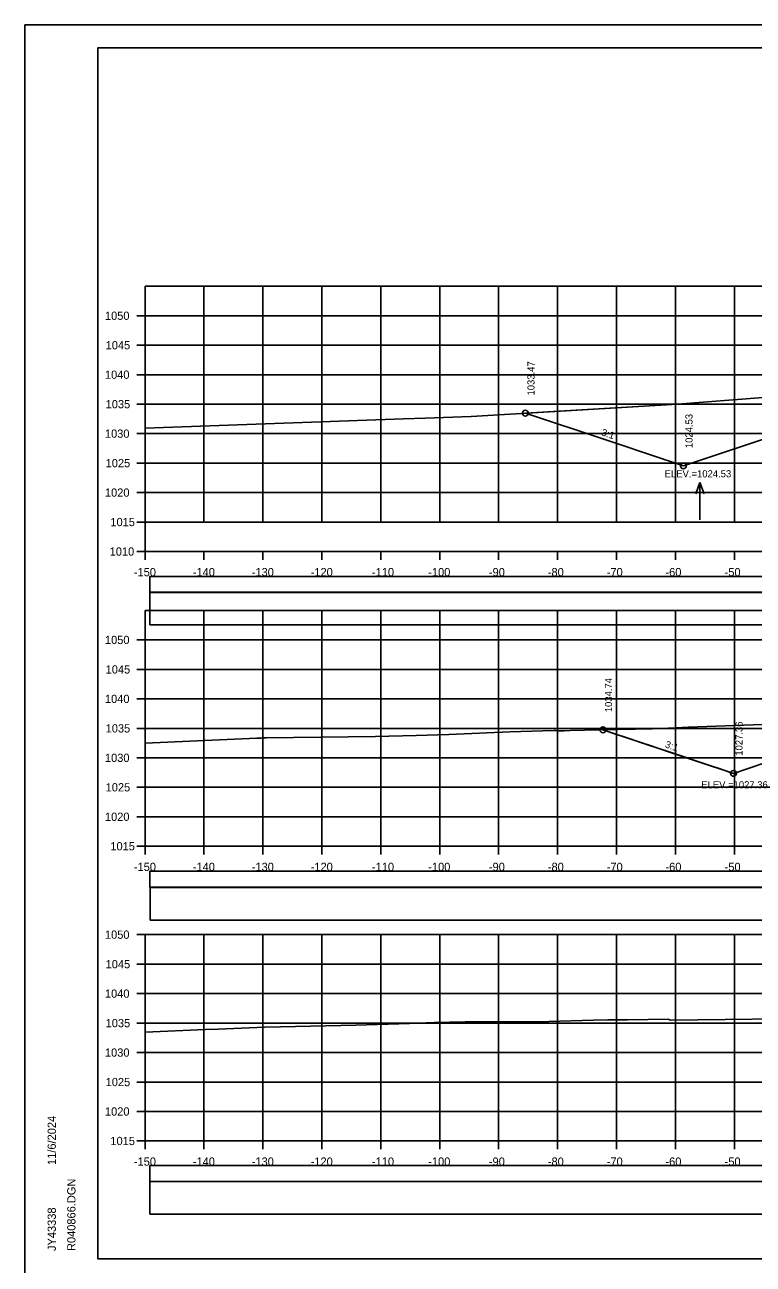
# Model space of a CAD drawing. Extents: x 1370565 to 1374448, y 301010 to 304637.
# Drawn here: x 1373198.4 to 1373322, y 301728.1 to 301938.3 of the extents above; entities that cross this region are included whole.
import ezdxf

# ---------------------------------------------------------------- set-up
doc = ezdxf.new("R2010")
doc.units = 0
for name, color, linetype in [('Default', 7, 'Continuous'), ('R_Axis', 7, 'Continuous'), ('R_Axis Annot', 7, 'Continuous'), ('R_Border', 7, 'Continuous'), ('R_Contours', 7, 'Continuous'), ('R_Drive', 7, 'Continuous'), ('R_Exist Surface', 7, 'Continuous'), ('R_Fin Surface', 7, 'Continuous'), ('R_Grid', 7, 'Continuous'), ('R_No Plot', 7, 'Continuous'), ('R_Water Annot', 7, 'Continuous'), ('R_Xsect Elev', 7, 'Continuous'), ('R_Xsect Slope', 7, 'Continuous')]:
    doc.layers.add(name, color=color, linetype=linetype)

msp = doc.modelspace()

# ---------------------------------------------------------------- linework, layer by layer
at = {"layer": 'Default'}
for points in [[(1373219.61, 301842.01), (1373518.02, 301842.01), (1373518.02, 301844.72), (1373219.61, 301844.72)], [(1373219.61, 301836.55), (1373517.91, 301836.55), (1373517.91, 301842.07), (1373219.61, 301842.07)], [(1373219.61, 301736.55), (1373517.91, 301736.55), (1373517.91, 301742.07), (1373219.61, 301742.07)]]:
    msp.add_lwpolyline(points, close=True, dxfattribs=at)
at = {"layer": 'R_Axis'}
for p, q in [((1373217.41, 301888.97), (1373218.81, 301888.97)), ((1373218.81, 301848.97), (1373218.81, 301888.97)), ((1373217.41, 301883.97), (1373218.81, 301883.97)), ((1373217.41, 301878.97), (1373218.81, 301878.97)), ((1373217.41, 301873.97), (1373218.81, 301873.97)), ((1373217.41, 301868.97), (1373218.81, 301868.97)), ((1373217.41, 301863.97), (1373218.81, 301863.97)), ((1373217.41, 301858.97), (1373218.81, 301858.97)), ((1373217.41, 301853.97), (1373218.81, 301853.97)), ((1373217.41, 301848.97), (1373218.81, 301848.97)), ((1373218.81, 301848.97), (1373518.81, 301848.97)), ((1373218.81, 301847.57), (1373218.81, 301848.97)), ((1373228.81, 301847.57), (1373228.81, 301848.97)), ((1373238.81, 301847.57), (1373238.81, 301848.97)), ((1373248.81, 301847.57), (1373248.81, 301848.97)), ((1373258.81, 301847.57), (1373258.81, 301848.97)), ((1373268.81, 301847.57), (1373268.81, 301848.97)), ((1373278.81, 301847.57), (1373278.81, 301848.97)), ((1373288.81, 301847.57), (1373288.81, 301848.97)), ((1373298.81, 301847.57), (1373298.81, 301848.97)), ((1373308.81, 301847.57), (1373308.81, 301848.97)), ((1373318.81, 301847.57), (1373318.81, 301848.97)), ((1373217.41, 301833.97), (1373218.81, 301833.97)), ((1373218.81, 301798.97), (1373218.81, 301833.97)), ((1373217.41, 301828.97), (1373218.81, 301828.97)), ((1373217.41, 301823.97), (1373218.81, 301823.97)), ((1373217.41, 301818.97), (1373218.81, 301818.97)), ((1373217.41, 301813.97), (1373218.81, 301813.97)), ((1373217.41, 301808.97), (1373218.81, 301808.97)), ((1373217.41, 301803.97), (1373218.81, 301803.97)), ((1373217.41, 301798.97), (1373218.81, 301798.97)), ((1373218.81, 301798.97), (1373518.81, 301798.97)), ((1373218.81, 301797.57), (1373218.81, 301798.97)), ((1373228.81, 301797.57), (1373228.81, 301798.97)), ((1373238.81, 301797.57), (1373238.81, 301798.97)), ((1373248.81, 301797.57), (1373248.81, 301798.97)), ((1373258.81, 301797.57), (1373258.81, 301798.97)), ((1373268.81, 301797.57), (1373268.81, 301798.97)), ((1373278.81, 301797.57), (1373278.81, 301798.97)), ((1373288.81, 301797.57), (1373288.81, 301798.97)), ((1373298.81, 301797.57), (1373298.81, 301798.97)), ((1373308.81, 301797.57), (1373308.81, 301798.97)), ((1373318.81, 301797.57), (1373318.81, 301798.97)), ((1373217.41, 301783.97), (1373218.81, 301783.97)), ((1373218.81, 301748.97), (1373218.81, 301783.97)), ((1373217.41, 301778.97), (1373218.81, 301778.97)), ((1373217.41, 301773.97), (1373218.81, 301773.97)), ((1373217.41, 301768.97), (1373218.81, 301768.97)), ((1373217.41, 301763.97), (1373218.81, 301763.97)), ((1373217.41, 301758.97), (1373218.81, 301758.97)), ((1373217.41, 301753.97), (1373218.81, 301753.97)), ((1373217.41, 301748.97), (1373218.81, 301748.97)), ((1373218.81, 301748.97), (1373518.81, 301748.97)), ((1373218.81, 301747.57), (1373218.81, 301748.97)), ((1373228.81, 301747.57), (1373228.81, 301748.97)), ((1373238.81, 301747.57), (1373238.81, 301748.97)), ((1373248.81, 301747.57), (1373248.81, 301748.97)), ((1373258.81, 301747.57), (1373258.81, 301748.97)), ((1373268.81, 301747.57), (1373268.81, 301748.97)), ((1373278.81, 301747.57), (1373278.81, 301748.97)), ((1373288.81, 301747.57), (1373288.81, 301748.97)), ((1373298.81, 301747.57), (1373298.81, 301748.97)), ((1373308.81, 301747.57), (1373308.81, 301748.97)), ((1373318.81, 301747.57), (1373318.81, 301748.97))]:
    msp.add_line(p, q, dxfattribs=at)
at = {"layer": 'R_Border'}
for p, q in [((1373210.81, 301934.43), (1373526.99, 301934.43)), ((1373210.81, 301728.97), (1373210.81, 301934.43)), ((1373210.81, 301728.97), (1373210.81, 301728.97)), ((1373526.99, 301728.97), (1373210.81, 301728.97))]:
    msp.add_line(p, q, dxfattribs=at)
at = {"layer": 'R_Contours'}
for points in [[(1373337.3, 301875.61), (1373330.04, 301875.36), (1373327.7, 301875.26), (1373323.67, 301875.09), (1373309.17, 301873.95), (1373283.35, 301872.44)], [(1373283.35, 301872.44), (1373296.85, 301867.95), (1373306.62, 301864.69), (1373307.06, 301864.54), (1373307.49, 301864.4), (1373310.16, 301863.51), (1373335.99, 301872.12), (1373339.81, 301873.39), (1373340.96, 301873.58), (1373342.79, 301873.89)], [(1373296.51, 301818.71), (1373298.84, 301817.94), (1373300.26, 301817.46), (1373302.75, 301816.63), (1373303.04, 301816.54), (1373303.63, 301816.34), (1373304.21, 301816.15), (1373307.98, 301814.89), (1373315.08, 301812.52), (1373316.15, 301812.17), (1373318.65, 301811.33), (1373326.66, 301814), (1373329.53, 301814.96), (1373332.85, 301816.06), (1373339.81, 301818.39), (1373340.71, 301818.53), (1373353.42, 301820.65)], [(1373352.45, 301820.64), (1373336.11, 301820.13), (1373326.67, 301819.76), (1373310.97, 301819.15), (1373308.86, 301819.07), (1373304.93, 301818.91), (1373299.01, 301818.77), (1373298.31, 301818.76), (1373296.51, 301818.71)]]:
    msp.add_lwpolyline(points, dxfattribs=at)
at = {"layer": 'R_Drive'}
for points in [[(1373219.61, 301792.01), (1373518.02, 301792.01), (1373518.02, 301794.72), (1373219.61, 301794.72)], [(1373219.61, 301742.07), (1373518.02, 301742.07), (1373518.02, 301744.78), (1373219.61, 301744.78)]]:
    msp.add_lwpolyline(points, close=True, dxfattribs=at)
at = {"layer": 'R_Exist Surface'}
for points in [[(1373218.81, 301869.88), (1373248.65, 301870.97), (1373262.66, 301871.48), (1373266.37, 301871.62), (1373274.15, 301871.9), (1373309.17, 301873.95), (1373323.67, 301875.09)], [(1373289.94, 301818.57), (1373290.96, 301818.58), (1373298.31, 301818.76), (1373299.01, 301818.77), (1373304.93, 301818.91), (1373308.86, 301819.07), (1373310.97, 301819.15), (1373326.67, 301819.76)], [(1373218.81, 301816.47), (1373237.76, 301817.29), (1373238.51, 301817.32), (1373238.85, 301817.34), (1373239.34, 301817.36), (1373257.92, 301817.61), (1373260.18, 301817.67), (1373264.84, 301817.78), (1373270.38, 301817.92), (1373280.71, 301818.36), (1373288.18, 301818.61), (1373288.5, 301818.58), (1373288.92, 301818.55), (1373289.06, 301818.54), (1373289.11, 301818.53), (1373289.94, 301818.57)], [(1373218.81, 301767.4), (1373229.08, 301767.88), (1373231.23, 301767.94), (1373239.15, 301768.28), (1373241.81, 301768.33), (1373254.6, 301768.61), (1373263.7, 301768.91), (1373267.93, 301769.08), (1373273.12, 301769.18), (1373274.59, 301769.17), (1373287.34, 301769.21), (1373294.87, 301769.45), (1373297.32, 301769.51), (1373297.54, 301769.51), (1373300.65, 301769.54), (1373307.61, 301769.61), (1373307.7, 301769.57), (1373307.95, 301769.47), (1373335.77, 301769.82)]]:
    msp.add_lwpolyline(points, dxfattribs=at)
at = {"layer": 'R_Fin Surface'}
for points in [[(1373283.37, 301872.44), (1373296.85, 301867.95), (1373306.62, 301864.69), (1373307.06, 301864.54), (1373307.49, 301864.4), (1373310.16, 301863.51), (1373335.99, 301872.12), (1373339.81, 301873.39), (1373353.81, 301875.73), (1373357.81, 301876.05), (1373368.81, 301876.96), (1373379.81, 301877.87), (1373383.81, 301878.2), (1373397.81, 301875.86), (1373425.23, 301866.73), (1373429.66, 301865.25), (1373443.87, 301872.3), (1373446.06, 301873.45)], [(1373296.07, 301818.86), (1373298.47, 301818.06), (1373299.9, 301817.58), (1373302.41, 301816.75), (1373302.71, 301816.65), (1373303.31, 301816.45), (1373303.9, 301816.25), (1373307.73, 301814.98), (1373314.99, 301812.55), (1373316.09, 301812.19), (1373318.65, 301811.33), (1373326.66, 301814), (1373329.53, 301814.96), (1373332.85, 301816.06), (1373339.81, 301818.39), (1373353.81, 301820.72), (1373357.81, 301821.05), (1373368.81, 301821.98), (1373379.81, 301822.9), (1373383.81, 301823.24), (1373397.81, 301820.91), (1373431.81, 301809.57), (1373444.26, 301815.8)]]:
    msp.add_lwpolyline(points, dxfattribs=at)
msp.add_lwpolyline([(1373219.66, 301786.44), (1373518.08, 301786.44), (1373518.08, 301791.96), (1373219.66, 301791.96)], close=True, dxfattribs=at)
at = {"layer": 'R_Grid'}
for p, q in [((1373218.81, 301893.97), (1373518.81, 301893.97)), ((1373218.81, 301853.97), (1373218.81, 301893.97)), ((1373228.81, 301853.97), (1373228.81, 301893.97)), ((1373238.81, 301853.97), (1373238.81, 301893.97)), ((1373248.81, 301853.97), (1373248.81, 301893.97)), ((1373258.81, 301853.97), (1373258.81, 301893.97)), ((1373268.81, 301853.97), (1373268.81, 301893.97)), ((1373278.81, 301853.97), (1373278.81, 301893.97)), ((1373288.81, 301853.97), (1373288.81, 301893.97)), ((1373298.81, 301853.97), (1373298.81, 301893.97)), ((1373308.81, 301853.97), (1373308.81, 301893.97)), ((1373318.81, 301853.97), (1373318.81, 301893.97)), ((1373218.81, 301888.97), (1373518.81, 301888.97)), ((1373218.81, 301883.97), (1373518.81, 301883.97)), ((1373218.81, 301878.97), (1373518.81, 301878.97)), ((1373218.81, 301873.97), (1373518.81, 301873.97)), ((1373218.81, 301868.97), (1373518.81, 301868.97)), ((1373218.81, 301863.97), (1373518.81, 301863.97)), ((1373218.81, 301858.97), (1373518.81, 301858.97)), ((1373218.81, 301853.97), (1373518.81, 301853.97)), ((1373218.81, 301838.97), (1373518.81, 301838.97)), ((1373218.81, 301798.97), (1373218.81, 301838.97)), ((1373228.81, 301798.97), (1373228.81, 301838.97)), ((1373238.81, 301798.97), (1373238.81, 301838.97)), ((1373248.81, 301798.97), (1373248.81, 301838.97)), ((1373258.81, 301798.97), (1373258.81, 301838.97)), ((1373268.81, 301798.97), (1373268.81, 301838.97)), ((1373278.81, 301798.97), (1373278.81, 301838.97)), ((1373288.81, 301798.97), (1373288.81, 301838.97)), ((1373298.81, 301798.97), (1373298.81, 301838.97)), ((1373308.81, 301798.97), (1373308.81, 301838.97)), ((1373318.81, 301798.97), (1373318.81, 301838.97)), ((1373218.81, 301833.97), (1373518.81, 301833.97)), ((1373218.81, 301828.97), (1373518.81, 301828.97)), ((1373218.81, 301823.97), (1373518.81, 301823.97)), ((1373218.81, 301818.97), (1373518.81, 301818.97)), ((1373218.81, 301813.97), (1373518.81, 301813.97)), ((1373218.81, 301808.97), (1373518.81, 301808.97)), ((1373218.81, 301803.97), (1373518.81, 301803.97)), ((1373218.81, 301798.97), (1373518.81, 301798.97)), ((1373218.81, 301783.97), (1373518.81, 301783.97)), ((1373218.81, 301748.97), (1373218.81, 301783.97)), ((1373228.81, 301748.97), (1373228.81, 301783.97)), ((1373238.81, 301748.97), (1373238.81, 301783.97)), ((1373248.81, 301748.97), (1373248.81, 301783.97)), ((1373258.81, 301748.97), (1373258.81, 301783.97)), ((1373268.81, 301748.97), (1373268.81, 301783.97)), ((1373278.81, 301748.97), (1373278.81, 301783.97)), ((1373288.81, 301748.97), (1373288.81, 301783.97)), ((1373298.81, 301748.97), (1373298.81, 301783.97)), ((1373308.81, 301748.97), (1373308.81, 301783.97)), ((1373318.81, 301748.97), (1373318.81, 301783.97)), ((1373218.81, 301778.97), (1373518.81, 301778.97)), ((1373218.81, 301773.97), (1373518.81, 301773.97)), ((1373218.81, 301768.97), (1373518.81, 301768.97)), ((1373218.81, 301763.97), (1373518.81, 301763.97)), ((1373218.81, 301758.97), (1373518.81, 301758.97)), ((1373218.81, 301753.97), (1373518.81, 301753.97)), ((1373218.81, 301748.97), (1373518.81, 301748.97))]:
    msp.add_line(p, q, dxfattribs=at)
at = {"layer": 'R_No Plot'}
msp.add_line((1373198.41, 301938.33), (1373531.75, 301938.33), dxfattribs=at)
for points in [[(1373198.41, 301938.33), (1373531.75, 301938.33), (1373531.75, 301724.99), (1373198.41, 301724.99)], [(1373444.73, 301934.43), (1373464.35, 301934.43), (1373464.35, 301924.55), (1373480.47, 301924.55), (1373503.67, 301924.55), (1373503.67, 301891.88), (1373526.87, 301891.88), (1373526.99, 301728.97), (1373210.81, 301728.97), (1373210.81, 301934.43)]]:
    msp.add_lwpolyline(points, close=True, dxfattribs=at)
for centre in [(1373283.35, 301872.44), (1373310.16, 301863.51), (1373296.51, 301818.71), (1373318.65, 301811.33)]:
    msp.add_circle(centre, 0.5, dxfattribs=at)
at = {"layer": 'R_Water Annot'}
for p, q in [((1373312.97, 301860.66), (1373312.27, 301858.73)), ((1373312.97, 301854.37), (1373312.97, 301860.66)), ((1373312.97, 301860.66), (1373313.67, 301858.73))]:
    msp.add_line(p, q, dxfattribs=at)

# ---------------------------------------------------------------- texts
at = {"layer": 'R_Axis Annot'}
for s, p in [('1050', (1373212.01, 301888.27)), ('1045', (1373212.13, 301883.27)), ('1040', (1373212.01, 301878.27)), ('1035', (1373212.13, 301873.27)), ('1030', (1373212.01, 301868.27)), ('1025', (1373212.13, 301863.27)), ('1020', (1373212.01, 301858.27)), ('1015', (1373212.93, 301853.27)), ('1010', (1373212.81, 301848.27)), ('-150', (1373216.92, 301844.77)), ('-140', (1373226.92, 301844.77)), ('-130', (1373236.92, 301844.77)), ('-120', (1373246.92, 301844.77)), ('-110', (1373257.32, 301844.77)), ('-100', (1373266.87, 301844.77)), ('-90', (1373277.16, 301844.77)), ('-80', (1373287.16, 301844.77)), ('-70', (1373297.16, 301844.77)), ('-60', (1373307.12, 301844.77)), ('-50', (1373317.16, 301844.77)), ('1050', (1373212.01, 301833.27)), ('1045', (1373212.13, 301828.27)), ('1040', (1373212.01, 301823.27)), ('1035', (1373212.13, 301818.27)), ('1030', (1373212.01, 301813.27)), ('1025', (1373212.13, 301808.27)), ('1020', (1373212.01, 301803.27)), ('1015', (1373212.93, 301798.27)), ('-150', (1373216.92, 301794.77)), ('-140', (1373226.92, 301794.77)), ('-130', (1373236.92, 301794.77)), ('-120', (1373246.92, 301794.77)), ('-110', (1373257.32, 301794.77)), ('-100', (1373266.87, 301794.77)), ('-90', (1373277.16, 301794.77)), ('-80', (1373287.16, 301794.77)), ('-70', (1373297.16, 301794.77)), ('-60', (1373307.12, 301794.77)), ('-50', (1373317.16, 301794.77)), ('1050', (1373212.01, 301783.27)), ('1045', (1373212.13, 301778.27)), ('1040', (1373212.01, 301773.27)), ('1035', (1373212.13, 301768.27)), ('1030', (1373212.01, 301763.27)), ('1025', (1373212.13, 301758.27)), ('1020', (1373212.01, 301753.27)), ('1015', (1373212.93, 301748.27)), ('-150', (1373216.92, 301744.77)), ('-140', (1373226.92, 301744.77)), ('-130', (1373236.92, 301744.77)), ('-120', (1373246.92, 301744.77)), ('-110', (1373257.32, 301744.77)), ('-100', (1373266.87, 301744.77)), ('-90', (1373277.16, 301744.77)), ('-80', (1373287.16, 301744.77)), ('-70', (1373297.16, 301744.77)), ('-60', (1373307.12, 301744.77)), ('-50', (1373317.16, 301744.77))]:
    msp.add_text(s, height=1.4, dxfattribs=at).set_placement(p)
at = {"layer": 'R_Border'}
for s, p in [('11/6/2024', (1373203.68, 301744.9)), ('R040866.DGN', (1373207.01, 301730.3)), ('JY43338', (1373203.68, 301730.3))]:
    msp.add_text(s, height=1.4, rotation=90, dxfattribs=at).set_placement(p)
at = {"layer": 'R_Xsect Elev'}
for s, p in [('1033.47', (1373284.9, 301875.44)), ('1024.53', (1373311.71, 301866.51)), ('1034.74', (1373298.06, 301821.71)), ('1027.36', (1373320.2, 301814.33))]:
    msp.add_text(s, height=1.2, rotation=90, dxfattribs=at).set_placement(p)
for s, p in [('ELEV.=1024.53', (1373306.99, 301861.56)), ('ELEV.=1027.36', (1373313.19, 301808.8))]:
    msp.add_text(s, height=1.2, dxfattribs=at).set_placement(p)
at = {"layer": 'R_Xsect Slope'}
for p in [(1373296.13, 301868.71), (1373306.95, 301815.76)]:
    msp.add_text('3:1', height=1.2, rotation=341.5668, dxfattribs=at).set_placement(p)

doc.saveas('drawing.dxf')
